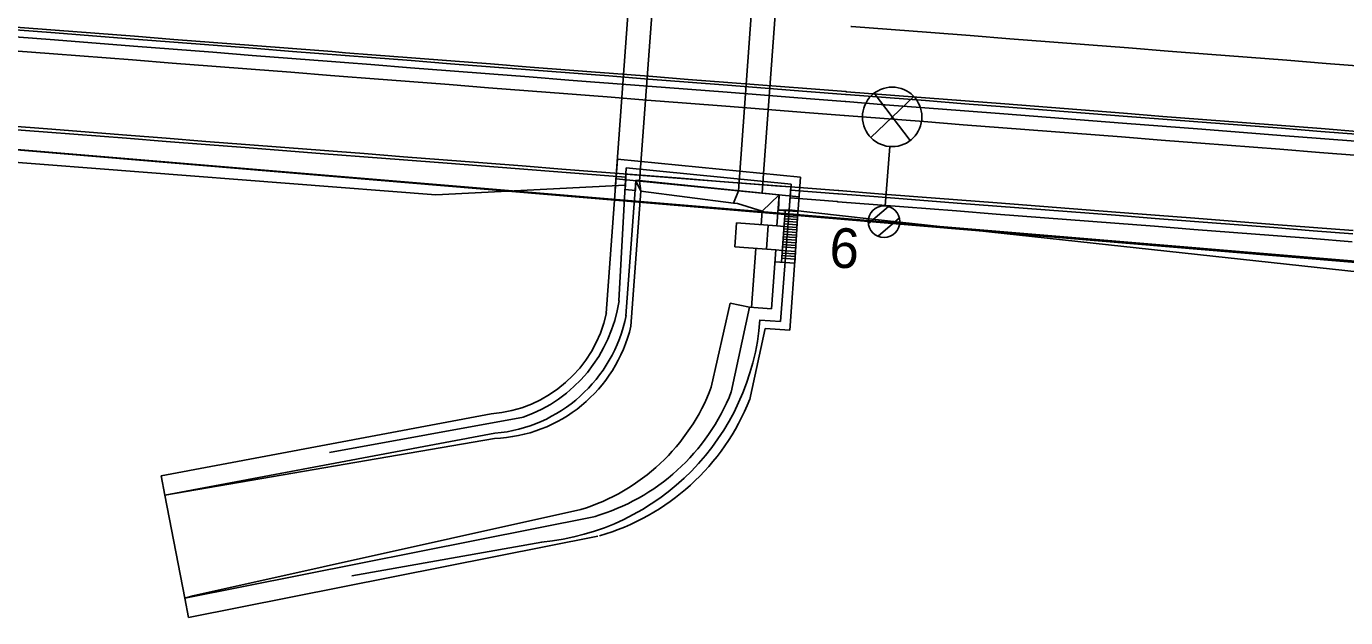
# Model space of a CAD drawing. Extents: x -669628 to -669207, y -977198 to -977075.
# Drawn here: x -669490.41 to -669457.17, y -977160.84 to -977145.94 of the extents above; entities that cross this region are included whole.
import ezdxf

# ---------------------------------------------------------------- set-up
doc = ezdxf.new("R2010")
doc.units = 0
for name, color, linetype in [('SO 01-20-01', 7, 'Continuous'), ('SO 01-86-01', 7, 'Continuous'), ('SO 11-10-01', 7, 'Continuous'), ('SO 11-12-01', 7, 'Continuous')]:
    doc.layers.add(name, color=color, linetype=linetype)

# ---------------------------------------------------------------- blocks, each defined once
blk = doc.blocks.new('POINT_DISPLAY')
blk.add_line((0, 0), (0, 0))

msp = doc.modelspace()

# ---------------------------------------------------------------- linework, layer by layer
at = {"layer": 'SO 01-20-01'}
for p, q in [((-669475.576, -977150.04), (-669474.546, -977136.022)), ((-669474.959, -977149.839), (-669473.947, -977136.066)), ((-669472.47, -977150.083), (-669471.452, -977136.221)), ((-669471.836, -977149.643), (-669470.854, -977136.265)), ((-669475.513, -977149.282), (-669475.799, -977153.166)), ((-669475.513, -977149.282), (-669470.904, -977149.735)), ((-669475.55, -977149.781), (-669470.941, -977150.233)), ((-669475.478, -977152.855), (-669475.294, -977149.507)), ((-669475.294, -977149.507), (-669471.139, -977149.914)), ((-669471.873, -977150.142), (-669471.836, -977149.643)), ((-669470.904, -977149.735), (-669470.998, -977151.003)), ((-669475.051, -977149.83), (-669475.302, -977153.236)), ((-669474.928, -977150.089), (-669475.179, -977153.495)), ((-669475.051, -977149.83), (-669474.928, -977150.089)), ((-669474.928, -977150.089), (-669474.959, -977149.839)), ((-669474.928, -977150.092), (-669472.589, -977150.39)), ((-669472.589, -977150.39), (-669472.47, -977150.083)), ((-669471.139, -977149.914), (-669471.404, -977153.375)), ((-669472.589, -977150.39), (-669472.494, -977150.405)), ((-669472.494, -977150.405), (-669471.87, -977150.593)), ((-669471.87, -977150.593), (-669471.439, -977150.187)), ((-669471.439, -977150.187), (-669471.496, -977150.966)), ((-669471.87, -977150.593), (-669471.895, -977150.937)), ((-669471.467, -977150.568), (-669470.968, -977150.604)), ((-669471.29, -977150.581), (-669471.386, -977151.884)), ((-669471.305, -977150.785), (-669470.983, -977150.809)), ((-669471.3, -977150.72), (-669470.979, -977150.744)), ((-669471.295, -977150.655), (-669470.974, -977150.679)), ((-669470.968, -977150.604), (-669471.05, -977151.909)), ((-669472.516, -977150.892), (-669472.561, -977151.497)), ((-669472.516, -977150.892), (-669471.496, -977150.966)), ((-669471.718, -977150.95), (-669471.763, -977151.555)), ((-669471.496, -977150.966), (-669471.319, -977150.979)), ((-669471.329, -977151.109), (-669471.007, -977151.133)), ((-669471.324, -977151.044), (-669471.002, -977151.068)), ((-669471.319, -977150.979), (-669470.998, -977151.003)), ((-669471.315, -977150.915), (-669470.993, -977150.938)), ((-669471.31, -977150.85), (-669470.988, -977150.873)), ((-669471.353, -977151.433), (-669471.031, -977151.457)), ((-669471.348, -977151.368), (-669471.026, -977151.392)), ((-669471.343, -977151.304), (-669471.021, -977151.327)), ((-669471.338, -977151.239), (-669471.017, -977151.262)), ((-669471.334, -977151.174), (-669471.012, -977151.198)), ((-669472.561, -977151.497), (-669471.527, -977151.573)), ((-669472.026, -977151.536), (-669472.135, -977153.021)), ((-669471.527, -977151.573), (-669471.636, -977153.058)), ((-669471.527, -977151.573), (-669471.364, -977151.585)), ((-669471.378, -977151.779), (-669471.043, -977151.804)), ((-669471.373, -977151.714), (-669471.038, -977151.739)), ((-669471.369, -977151.65), (-669471.033, -977151.674)), ((-669471.364, -977151.585), (-669471.028, -977151.609)), ((-669471.357, -977151.498), (-669471.036, -977151.522)), ((-669471.028, -977151.609), (-669471.174, -977153.593)), ((-669471.549, -977151.872), (-669471.05, -977151.909)), ((-669473.152, -977155.031), (-669472.678, -977152.912)), ((-669472.189, -977153.017), (-669472.678, -977152.912)), ((-669472.649, -977155.155), (-669472.189, -977153.017)), ((-669472.189, -977153.017), (-669471.636, -977153.058)), ((-669471.404, -977153.375), (-669471.925, -977153.343)), ((-669472.16, -977155.261), (-669471.792, -977153.548)), ((-669471.792, -977153.548), (-669471.174, -977153.593)), ((-669472.184, -977155.34), (-669472.16, -977155.261)), ((-669478.697, -977155.702), (-669487.016, -977157.264)), ((-669482.773, -977156.673), (-669477.887, -977155.788)), ((-669478.605, -977156.193), (-669486.924, -977157.755)), ((-669478.615, -977156.322), (-669486.924, -977157.755)), ((-669487.016, -977157.264), (-669486.924, -977157.755)), ((-669486.924, -977157.755), (-669486.42, -977160.347)), ((-669476.109, -977158.295), (-669486.42, -977160.347)), ((-669476.439, -977158.113), (-669486.218, -977160.292)), ((-669476.011, -977158.785), (-669486.323, -977160.837)), ((-669477.419, -977158.934), (-669482.209, -977159.783)), ((-669486.218, -977160.292), (-669486.42, -977160.347)), ((-669486.42, -977160.347), (-669486.323, -977160.837))]:
    msp.add_line(p, q, dxfattribs=at)
for centre, radius, start, end in [((-669478.939, -977152.5), 3.211, 274.3323, 348.1321), ((-669478.933, -977152.504), 3.704, 275.1074, 348.7282), ((-669478.75, -977152.656), 3.669, 272.0762, 346.7766), ((-669477.574, -977153.204), 5.298, 286.0891, 338.4449), ((-669477.574, -977153.204), 5.798, 286.0404, 338.4235)]:
    msp.add_arc(centre, radius, start, end, dxfattribs=at)
for centre, major_axis, ratio, start_param, end_param in [((-669479.113, -977152.324), (-0.268, 3.665), 0.999859, 3.40753, 4.494824), ((-669477.988, -977152.881), (5.162, -3.214), 0.99986, 5.361213, 6.765491), ((-669478.008, -977153.148), (3.646, -3.732), 0.9906, 5.811258, 6.713935)]:
    msp.add_ellipse(centre, major_axis=major_axis, ratio=ratio, start_param=start_param, end_param=end_param, dxfattribs=at)
at = {"layer": 'SO 01-86-01'}
for p, q in [((-669445.341, -977152.857), (-669517.763, -977146.78)), ((-669445.341, -977152.857), (-669517.763, -977146.78)), ((-669443.485, -977152.976), (-669517.763, -977146.78)), ((-669469.135, -977148.736), (-669468.05, -977147.704)), ((-669469.049, -977147.626), (-669468.137, -977148.813)), ((-669468.651, -977148.966), (-669468.767, -977150.462)), ((-669469.192, -977150.91), (-669468.689, -977150.479)), ((-669468.948, -977151.227), (-669468.411, -977150.767))]:
    msp.add_line(p, q, dxfattribs=at)
for centre, radius in [((-669468.593, -977148.22), 0.749), ((-669468.798, -977150.86), 0.4)]:
    msp.add_circle(centre, radius, dxfattribs=at)
at = {"layer": 'SO 11-10-01'}
for p, q in [((-669469.632, -977145.939), (-669469.616, -977145.94)), ((-669469.616, -977145.94), (-669468.619, -977146.018)), ((-669468.619, -977146.018), (-669467.622, -977146.095)), ((-669467.622, -977146.095), (-669466.625, -977146.173)), ((-669466.625, -977146.173), (-669465.628, -977146.25)), ((-669465.628, -977146.25), (-669464.631, -977146.328)), ((-669464.631, -977146.328), (-669463.634, -977146.406)), ((-669463.634, -977146.406), (-669462.637, -977146.483)), ((-669462.637, -977146.483), (-669461.641, -977146.561)), ((-669461.641, -977146.561), (-669460.644, -977146.638)), ((-669460.644, -977146.638), (-669459.647, -977146.716)), ((-669459.647, -977146.716), (-669458.65, -977146.794)), ((-669458.65, -977146.794), (-669457.653, -977146.871)), ((-669457.653, -977146.871), (-669456.656, -977146.949))]:
    msp.add_line(p, q, dxfattribs=at)
at = {"layer": 'SO 11-12-01'}
for p, q in [((-669490.687, -977146.025), (-669489.69, -977146.103)), ((-669490.681, -977145.955), (-669489.684, -977146.033)), ((-669489.69, -977146.103), (-669487.696, -977146.258)), ((-669489.684, -977146.033), (-669488.687, -977146.11)), ((-669488.687, -977146.11), (-669487.69, -977146.188)), ((-669490.7, -977146.204), (-669489.704, -977146.282)), ((-669489.704, -977146.282), (-669487.71, -977146.437)), ((-669487.71, -977146.437), (-669486.713, -977146.515)), ((-669487.696, -977146.258), (-669486.699, -977146.335)), ((-669487.69, -977146.188), (-669486.693, -977146.266)), ((-669486.699, -977146.335), (-669485.702, -977146.413)), ((-669486.693, -977146.266), (-669485.696, -977146.343)), ((-669485.702, -977146.413), (-669484.705, -977146.491)), ((-669485.696, -977146.343), (-669484.699, -977146.421)), ((-669484.699, -977146.421), (-669483.702, -977146.498)), ((-669490.728, -977146.553), (-669489.731, -977146.631)), ((-669489.731, -977146.631), (-669487.737, -977146.786)), ((-669487.737, -977146.786), (-669486.74, -977146.864)), ((-669486.713, -977146.515), (-669485.716, -977146.593)), ((-669485.716, -977146.593), (-669484.719, -977146.67)), ((-669484.719, -977146.67), (-669483.722, -977146.748)), ((-669484.705, -977146.491), (-669483.708, -977146.568)), ((-669483.722, -977146.748), (-669482.725, -977146.825)), ((-669483.708, -977146.568), (-669482.38, -977146.672)), ((-669483.702, -977146.498), (-669482.705, -977146.576)), ((-669482.705, -977146.576), (-669482.374, -977146.602)), ((-669482.38, -977146.672), (-669481.714, -977146.723)), ((-669482.374, -977146.602), (-669481.708, -977146.654)), ((-669481.714, -977146.723), (-669480.717, -977146.801)), ((-669481.708, -977146.654), (-669480.711, -977146.731)), ((-669480.717, -977146.801), (-669479.72, -977146.879)), ((-669480.711, -977146.731), (-669479.714, -977146.809)), ((-669486.74, -977146.864), (-669485.743, -977146.941)), ((-669485.743, -977146.941), (-669484.746, -977147.019)), ((-669484.746, -977147.019), (-669483.749, -977147.097)), ((-669483.749, -977147.097), (-669482.752, -977147.174)), ((-669482.725, -977146.825), (-669482.394, -977146.851)), ((-669482.394, -977146.851), (-669481.728, -977146.903)), ((-669481.728, -977146.903), (-669480.731, -977146.981)), ((-669480.731, -977146.981), (-669479.734, -977147.058)), ((-669479.734, -977147.058), (-669478.737, -977147.136)), ((-669479.72, -977146.879), (-669478.723, -977146.956)), ((-669479.714, -977146.809), (-669478.717, -977146.887)), ((-669478.737, -977147.136), (-669477.74, -977147.213)), ((-669478.723, -977146.956), (-669477.726, -977147.034)), ((-669478.717, -977146.887), (-669477.72, -977146.964)), ((-669477.726, -977147.034), (-669476.729, -977147.112)), ((-669477.72, -977146.964), (-669476.723, -977147.042)), ((-669476.729, -977147.112), (-669476.073, -977147.163)), ((-669476.723, -977147.042), (-669476.067, -977147.093)), ((-669476.067, -977147.093), (-669475.726, -977147.119)), ((-669475.726, -977147.119), (-669474.729, -977147.197)), ((-669482.752, -977147.174), (-669482.421, -977147.2)), ((-669482.421, -977147.2), (-669481.755, -977147.252)), ((-669481.755, -977147.252), (-669480.758, -977147.329)), ((-669480.758, -977147.329), (-669479.761, -977147.407)), ((-669479.761, -977147.407), (-669478.764, -977147.485)), ((-669477.74, -977147.213), (-669476.743, -977147.291)), ((-669476.743, -977147.291), (-669476.087, -977147.342)), ((-669476.087, -977147.342), (-669475.746, -977147.369)), ((-669476.073, -977147.163), (-669475.732, -977147.189)), ((-669475.746, -977147.369), (-669474.749, -977147.446)), ((-669475.732, -977147.189), (-669474.735, -977147.267)), ((-669474.749, -977147.446), (-669473.752, -977147.524)), ((-669474.735, -977147.267), (-669473.738, -977147.344)), ((-669474.729, -977147.197), (-669473.732, -977147.275)), ((-669473.738, -977147.344), (-669472.741, -977147.422)), ((-669473.732, -977147.275), (-669472.735, -977147.352)), ((-669472.741, -977147.422), (-669470.747, -977147.577)), ((-669472.735, -977147.352), (-669470.741, -977147.507)), ((-669478.764, -977147.485), (-669477.767, -977147.562)), ((-669477.767, -977147.562), (-669476.77, -977147.64)), ((-669476.77, -977147.64), (-669476.114, -977147.691)), ((-669476.114, -977147.691), (-669475.773, -977147.718)), ((-669475.773, -977147.718), (-669474.776, -977147.795)), ((-669474.776, -977147.795), (-669473.779, -977147.873)), ((-669473.752, -977147.524), (-669472.755, -977147.601)), ((-669472.755, -977147.601), (-669470.761, -977147.757)), ((-669470.761, -977147.757), (-669469.78, -977147.833)), ((-669470.747, -977147.577), (-669469.766, -977147.654)), ((-669470.741, -977147.507), (-669469.76, -977147.584)), ((-669469.766, -977147.654), (-669469.75, -977147.655)), ((-669469.76, -977147.584), (-669469.744, -977147.585)), ((-669469.75, -977147.655), (-669468.753, -977147.732)), ((-669469.744, -977147.585), (-669468.747, -977147.663)), ((-669468.753, -977147.732), (-669467.756, -977147.81)), ((-669468.747, -977147.663), (-669467.75, -977147.74)), ((-669467.75, -977147.74), (-669466.753, -977147.818)), ((-669473.779, -977147.873), (-669472.782, -977147.95)), ((-669472.782, -977147.95), (-669470.788, -977148.106)), ((-669470.788, -977148.106), (-669469.807, -977148.182)), ((-669469.78, -977147.833), (-669469.764, -977147.834)), ((-669469.764, -977147.834), (-669468.767, -977147.912)), ((-669468.767, -977147.912), (-669467.77, -977147.989)), ((-669467.77, -977147.989), (-669466.773, -977148.067)), ((-669467.756, -977147.81), (-669466.759, -977147.888)), ((-669466.773, -977148.067), (-669465.776, -977148.145)), ((-669466.759, -977147.888), (-669465.762, -977147.965)), ((-669466.753, -977147.818), (-669465.756, -977147.895)), ((-669465.762, -977147.965), (-669462.771, -977148.198)), ((-669465.756, -977147.895), (-669462.766, -977148.128)), ((-669462.766, -977148.128), (-669461.769, -977148.206)), ((-669490.875, -977148.448), (-669489.878, -977148.525)), ((-669469.807, -977148.182), (-669469.791, -977148.183)), ((-669469.791, -977148.183), (-669468.794, -977148.261)), ((-669468.794, -977148.261), (-669467.797, -977148.338)), ((-669467.797, -977148.338), (-669466.8, -977148.416)), ((-669466.8, -977148.416), (-669465.803, -977148.494)), ((-669465.776, -977148.145), (-669462.785, -977148.377)), ((-669462.785, -977148.377), (-669461.788, -977148.455)), ((-669462.771, -977148.198), (-669461.774, -977148.276)), ((-669461.788, -977148.455), (-669460.791, -977148.533)), ((-669461.774, -977148.276), (-669460.777, -977148.353)), ((-669461.769, -977148.206), (-669460.772, -977148.283)), ((-669460.777, -977148.353), (-669458.783, -977148.508)), ((-669460.772, -977148.283), (-669459.775, -977148.361)), ((-669459.775, -977148.361), (-669458.778, -977148.439)), ((-669458.778, -977148.439), (-669457.781, -977148.516)), ((-669490.881, -977148.527), (-669489.884, -977148.605)), ((-669489.884, -977148.605), (-669487.89, -977148.76)), ((-669489.878, -977148.525), (-669487.884, -977148.681)), ((-669487.89, -977148.76), (-669486.893, -977148.838)), ((-669487.884, -977148.681), (-669486.887, -977148.758)), ((-669486.887, -977148.758), (-669485.89, -977148.836)), ((-669465.803, -977148.494), (-669462.812, -977148.726)), ((-669462.812, -977148.726), (-669461.815, -977148.804)), ((-669460.791, -977148.533), (-669458.797, -977148.688)), ((-669458.797, -977148.688), (-669457.8, -977148.765)), ((-669458.783, -977148.508), (-669457.786, -977148.586)), ((-669457.8, -977148.765), (-669456.803, -977148.843)), ((-669457.786, -977148.586), (-669456.789, -977148.664)), ((-669457.781, -977148.516), (-669456.784, -977148.594)), ((-669497.465, -977148.84), (-669480.094, -977150.182)), ((-669486.893, -977148.838), (-669485.896, -977148.915)), ((-669485.896, -977148.915), (-669484.899, -977148.993)), ((-669485.89, -977148.836), (-669484.893, -977148.913)), ((-669484.899, -977148.993), (-669482.905, -977149.148)), ((-669484.893, -977148.913), (-669483.896, -977148.991)), ((-669483.896, -977148.991), (-669482.899, -977149.069)), ((-669482.899, -977149.069), (-669482.568, -977149.094)), ((-669482.568, -977149.094), (-669481.902, -977149.146)), ((-669461.815, -977148.804), (-669460.818, -977148.882)), ((-669460.818, -977148.882), (-669458.824, -977149.037)), ((-669458.824, -977149.037), (-669457.827, -977149.114)), ((-669457.827, -977149.114), (-669456.83, -977149.192)), ((-669482.905, -977149.148), (-669482.574, -977149.174)), ((-669482.574, -977149.174), (-669481.908, -977149.226)), ((-669481.908, -977149.226), (-669480.911, -977149.304)), ((-669481.902, -977149.146), (-669480.905, -977149.224)), ((-669480.911, -977149.304), (-669479.914, -977149.381)), ((-669480.905, -977149.224), (-669479.908, -977149.301)), ((-669479.914, -977149.381), (-669475.307, -977149.74)), ((-669479.908, -977149.301), (-669478.911, -977149.379)), ((-669478.911, -977149.379), (-669477.914, -977149.457)), ((-669477.914, -977149.457), (-669476.917, -977149.534)), ((-669476.917, -977149.534), (-669476.261, -977149.585)), ((-669476.261, -977149.585), (-669475.92, -977149.612)), ((-669475.92, -977149.612), (-669474.923, -977149.689)), ((-669475.309, -977149.787), (-669475.324, -977150.051)), ((-669475.302, -977149.66), (-669475.309, -977149.787)), ((-669471.425, -977149.962), (-669475.302, -977149.66)), ((-669474.923, -977149.689), (-669473.926, -977149.767)), ((-669473.926, -977149.767), (-669472.929, -977149.845)), ((-669480.094, -977150.182), (-669475.318, -977149.94)), ((-669475.324, -977150.051), (-669475.059, -977150.075)), ((-669475.059, -977150.075), (-669475.051, -977149.814)), ((-669475.051, -977149.814), (-669471.439, -977150.187)), ((-669472.929, -977149.845), (-669470.935, -977150)), ((-669471.144, -977149.984), (-669471.425, -977149.962)), ((-669471.189, -977150.565), (-669471.144, -977149.984)), ((-669471.15, -977150.063), (-669469.96, -977150.156)), ((-669470.935, -977150), (-669469.954, -977150.076)), ((-669469.954, -977150.076), (-669469.938, -977150.077)), ((-669469.938, -977150.077), (-669468.941, -977150.155)), ((-669471.439, -977150.187), (-669471.462, -977150.568)), ((-669471.166, -977150.263), (-669469.976, -977150.355)), ((-669471.166, -977150.263), (-669469.976, -977150.355)), ((-669469.976, -977150.355), (-669469.96, -977150.357)), ((-669469.976, -977150.355), (-669469.96, -977150.357)), ((-669469.96, -977150.156), (-669469.945, -977150.157)), ((-669469.96, -977150.357), (-669468.963, -977150.434)), ((-669469.96, -977150.357), (-669468.963, -977150.434)), ((-669469.945, -977150.157), (-669468.948, -977150.235)), ((-669468.963, -977150.434), (-669466.969, -977150.589)), ((-669468.963, -977150.434), (-669466.969, -977150.589)), ((-669468.948, -977150.235), (-669466.954, -977150.39)), ((-669468.941, -977150.155), (-669467.944, -977150.233)), ((-669467.944, -977150.233), (-669466.947, -977150.31)), ((-669466.954, -977150.39), (-669465.957, -977150.468)), ((-669466.947, -977150.31), (-669465.951, -977150.388)), ((-669465.951, -977150.388), (-669462.96, -977150.621)), ((-669471.462, -977150.568), (-669471.189, -977150.565)), ((-669471.189, -977150.565), (-669469.174, -977150.785)), ((-669469.174, -977150.785), (-669453.419, -977152.5)), ((-669466.969, -977150.589), (-669465.972, -977150.667)), ((-669466.969, -977150.589), (-669465.972, -977150.667)), ((-669465.972, -977150.667), (-669462.981, -977150.9)), ((-669465.972, -977150.667), (-669462.981, -977150.9)), ((-669465.957, -977150.468), (-669462.966, -977150.7)), ((-669462.966, -977150.7), (-669461.969, -977150.778)), ((-669462.96, -977150.621), (-669461.963, -977150.698)), ((-669461.969, -977150.778), (-669460.972, -977150.856)), ((-669461.963, -977150.698), (-669460.966, -977150.776)), ((-669460.966, -977150.776), (-669458.972, -977150.931)), ((-669462.981, -977150.9), (-669461.984, -977150.977)), ((-669462.981, -977150.9), (-669461.984, -977150.977)), ((-669461.984, -977150.977), (-669460.987, -977151.055)), ((-669461.984, -977150.977), (-669460.987, -977151.055)), ((-669460.987, -977151.055), (-669458.993, -977151.21)), ((-669460.987, -977151.055), (-669458.993, -977151.21)), ((-669460.972, -977150.856), (-669458.978, -977151.011)), ((-669458.978, -977151.011), (-669457.981, -977151.088)), ((-669458.972, -977150.931), (-669457.975, -977151.009)), ((-669457.981, -977151.088), (-669456.984, -977151.166)), ((-669457.975, -977151.009), (-669456.978, -977151.086)), ((-669458.993, -977151.21), (-669457.996, -977151.288)), ((-669458.993, -977151.21), (-669457.996, -977151.288)), ((-669457.996, -977151.288), (-669456.999, -977151.365)), ((-669457.996, -977151.288), (-669456.999, -977151.365))]:
    msp.add_line(p, q, dxfattribs=at)

# ---------------------------------------------------------------- block references
at = {"layer": 'SO 01-86-01', "rotation": -4.450857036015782}
msp.add_blockref('POINT_DISPLAY', (-669468.798, -977150.86), dxfattribs=at)

# ---------------------------------------------------------------- texts
at = {"layer": 'SO 01-86-01'}
msp.add_text('6', height=1, rotation=356.1, dxfattribs=at).set_placement((-669470.2, -977152))

doc.saveas('drawing.dxf')
